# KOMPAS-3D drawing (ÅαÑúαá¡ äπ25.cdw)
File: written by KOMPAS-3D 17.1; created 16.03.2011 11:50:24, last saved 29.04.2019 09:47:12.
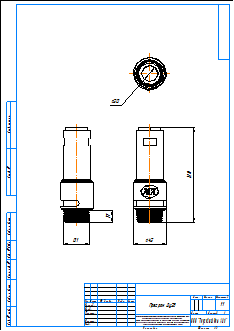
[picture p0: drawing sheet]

Title block, sheet 1: name: Прегран Ду25; material: Внимание! Данный продукт является объектом авторского права ООО «Торговый Дом АДЛ». / Запрещается изменение, копирование, распространение / (в том числе путем копирования на другие сайты и ресурсы в Интернете) / или любое иное использование информации и объектов без предварительного / согласия правообладателя (ООО «Торговый Дом АДЛ»).; scale: 1:1; sheets: 1; organisation: ООО "Торговый дом АДЛ"; sheet format: A3; stored path: C:\Users\tra\Desktop\2д чертежи\Предохранительные клапаны ПРЕГРАН\ПРЕГРАН 495\ПРЕГРАН КПП 495-05-25-ОМЗ\KOMPAS 2D\Прегран Ду25.cdw

Views: Спереди 1, Проекционный вид 2, Проекционный вид 3
Dimensions and other numbers on the sheet: 120; 42; 1; 17; 20; 1:1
